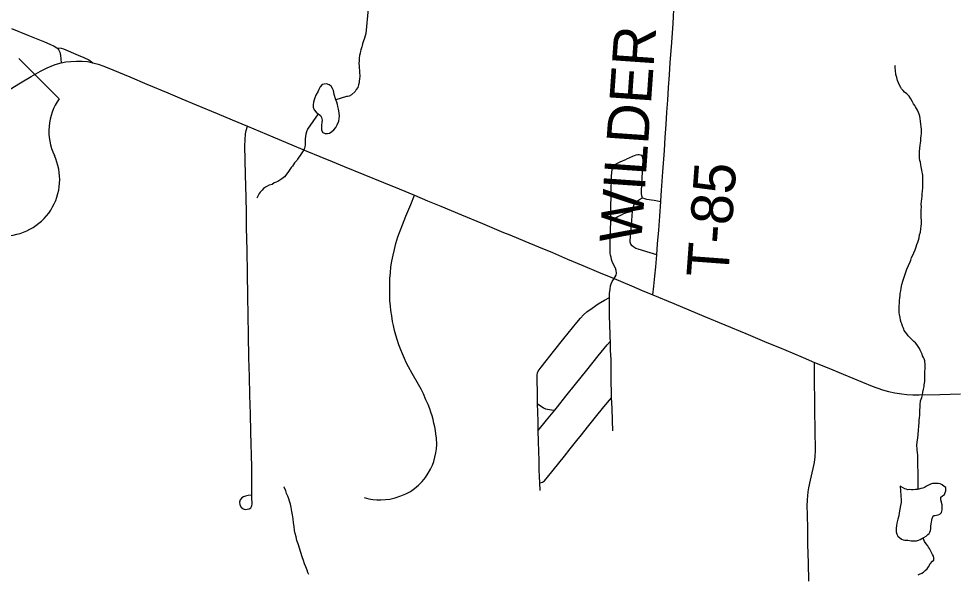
# Model space of a CAD drawing. Extents: x 103424 to 290657, y 38711 to 110967.
# Drawn here: x 127210 to 133964, y 99466 to 103483 of the extents above; entities that cross this region are included whole.
import ezdxf

# ---------------------------------------------------------------- set-up
doc = ezdxf.new("R2010")
doc.units = 0
for name, color, linetype in [('GM_X_County_Road', 7, 'Continuous'), ('GM_X_Minor_Lake', 7, 'Continuous'), ('GM_X_Minor_River', 7, 'Continuous'), ('GM_X_Township_Road', 7, 'Continuous'), ('GM_X_Township_Road_Text', 7, 'Continuous'), ('GM_X_US_Route', 7, 'Continuous'), ('GM_X_US_Shield', 7, 'Continuous')]:
    doc.layers.add(name, color=color, linetype=linetype)

msp = doc.modelspace()

# ---------------------------------------------------------------- linework, layer by layer
at = {"layer": 'GM_X_County_Road'}
for points in [[(127159.4, 103413.1), (127277.7, 103364.5), (127396.1, 103315.9), (127436.7, 103299), (127465.7, 103285.1), (127486.7, 103273.3), (127493.7, 103266.3), (127501.1, 103256), (127507.9, 103241.4), (127513.3, 103217.3), (127515.7, 103193.2), (127516.5, 103163.7)], [(127486.7, 103273.3), (127516.6, 103270), (127533.5, 103264.5), (127641.3, 103218.6), (127681, 103202.4), (127717.7, 103185.4), (127747, 103165.1)]]:
    msp.add_lwpolyline(points, dxfattribs=at)
at = {"layer": 'GM_X_Minor_Lake'}
for points in [[(129503, 102896.7), (129490.7, 102934.9), (129488.5, 102951), (129484.4, 102965.1), (129478.3, 102979.1), (129468.1, 102995.2), (129453.9, 103005.2), (129435.8, 103011.1), (129417.7, 103011), (129403.6, 103006.9), (129389.6, 102990.6), (129379.7, 102972.4), (129373.7, 102958.3), (129357.8, 102929.9), (129349.9, 102911.7), (129346, 102897.6), (129340.1, 102879.4), (129338.2, 102861.3), (129338.3, 102843.1), (129344.5, 102825), (129360.7, 102807), (129374.9, 102795), (129391.1, 102783), (129399.2, 102768.9), (129403.3, 102750.8), (129401.5, 102732.6), (129397.6, 102714.5), (129397.7, 102696.3), (129399.8, 102678.2), (129408, 102660.1)], [(129408, 102660.1), (129424.1, 102654.2), (129442.2, 102654.3), (129456.3, 102656.4), (129474.4, 102668.6), (129488.4, 102678.8), (129502.3, 102697), (129512.3, 102715.3), (129524.2, 102743.6), (129527.9, 102779.9), (129523.7, 102816.2), (129521.6, 102830.3), (129517.4, 102848.4), (129515.3, 102862.5), (129509.2, 102880.6), (129503, 102896.7)], [(133587, 100003.3), (133587.9, 99986.3), (133582.3, 99964), (133578.7, 99937.7), (133573.1, 99911.3), (133569.5, 99889), (133563.9, 99864.7), (133556.3, 99836.3), (133554.7, 99816), (133550.9, 99799.8), (133551.2, 99785.7), (133551.4, 99773.5), (133555.7, 99757.5), (133564.1, 99741.4), (133590.7, 99719.7), (133600.9, 99715.8), (133613, 99714), (133623.1, 99714.2), (133635.2, 99712.4), (133647.4, 99710.6), (133659.5, 99708.8), (133675.7, 99709.1), (133697.8, 99709.5), (133711.9, 99713.8), (133723.9, 99718.1), (133737.9, 99724.4), (133751.9, 99732.7), (133767.9, 99743.1), (133779.8, 99753.4), (133789.7, 99761.7), (133795.6, 99771.9), (133799.4, 99784.1), (133801.3, 99794.2), (133803, 99812.4), (133804.6, 99832.6), (133806.4, 99842.8), (133808.2, 99856.9), (133812, 99869.1), (133821.7, 99891.5), (133831.8, 99891.7), (133841.8, 99893.9), (133855.9, 99896.2), (133868, 99900.4), (133877.8, 99912.7), (133881.7, 99922.9), (133883.5, 99933.1), (133883.3, 99943.1), (133883.1, 99955.3), (133882.9, 99969.4), (133874.2, 100003.6), (133873.8, 100023.8), (133885.7, 100034.1), (133899.7, 100044.4), (133905.5, 100056.7), (133909.3, 100070.9), (133910.9, 100093.1), (133898.7, 100101), (133884.3, 100112.9), (133870.1, 100120.7), (133853.9, 100122.4), (133843.8, 100122.2), (133833.7, 100122), (133823.6, 100121.9), (133813.5, 100121.7), (133799.5, 100117.4), (133785.5, 100111.1), (133769.5, 100102.7), (133755.5, 100094.4), (133743.5, 100090.1), (133729.4, 100085.8), (133715.4, 100081.5), (133705.3, 100079.3), (133691.2, 100079.1), (133675.1, 100076.8), (133661, 100076.5), (133648.8, 100078.3), (133636.7, 100078.1), (133624.6, 100081.9), (133614.4, 100083.8), (133579.8, 100103.4)], [(133579.8, 100103.4), (133587, 100003.3)]]:
    msp.add_lwpolyline(points, dxfattribs=at)
at = {"layer": 'GM_X_Minor_River'}
for points in [[(129736, 103553.5), (129718.2, 103376.9), (129708.5, 103342.5), (129700.7, 103316.1), (129694.8, 103302), (129693, 103289.8), (129689, 103279.7), (129683.2, 103257.4), (129679.3, 103247.3), (129677.5, 103233.1), (129673.6, 103216.9), (129671.8, 103198.7), (129670, 103180.5), (129668.2, 103160.3), (129670.4, 103142.1), (129670.6, 103126), (129672.8, 103111.9), (129673, 103093.7), (129675.3, 103069.5), (129673.6, 103047.2), (129671.7, 103033.1), (129669.8, 103020.9), (129666, 103004.7), (129660.1, 102986.5), (129650.2, 102972.3), (129642.3, 102958), (129614.3, 102933.5), (129598.2, 102923.3), (129586.2, 102921.1), (129580.1, 102921.1), (129503, 102896.7)], [(133731.9, 101983.1), (133733.6, 102001.3), (133735.1, 102027.6), (133732.8, 102043.7), (133732.5, 102057.8), (133732.3, 102072), (133732, 102086.1), (133731.7, 102102.3), (133733.4, 102120.5), (133733, 102142.7), (133734.7, 102160.9), (133736.4, 102181.1), (133738.1, 102199.3), (133739.8, 102215.5), (133741.4, 102239.8), (133743.1, 102258), (133744.7, 102278.2), (133744.4, 102298.5), (133744, 102318.6), (133743.7, 102336.8), (133743.4, 102350.9), (133741.2, 102363), (133739, 102373.1), (133736.7, 102387.2), (133734.5, 102399.3), (133732.2, 102413.4), (133729.9, 102427.5), (133727.6, 102445.6), (133723.4, 102457.7), (133721, 102473.8), (133720.7, 102491.9), (133720.4, 102510.1), (133720.1, 102524.3), (133725.4, 102568.8), (133727.2, 102583), (133728.9, 102601.2), (133730.5, 102619.4), (133732.3, 102635.6), (133734, 102651.8), (133733.7, 102665.9), (133733.4, 102684.1), (133733.1, 102702.3), (133730.7, 102720.4), (133728.3, 102742.6), (133723.9, 102762.7), (133721.6, 102778.8), (133717.3, 102792.9), (133713.1, 102804.9), (133704.7, 102823), (133698.4, 102835), (133692.2, 102845), (133685.9, 102854.9), (133677.7, 102866.9), (133669.3, 102882.9), (133656.8, 102904.9), (133644.4, 102922.9), (133627.9, 102940.8), (133611.6, 102952.6), (133601.3, 102964.5), (133590.9, 102976.5), (133584.7, 102986.4), (133572.3, 103006.4), (133568, 103018.5), (133561.6, 103036.5), (133555.2, 103058.6), (133548.7, 103078.7), (133546.2, 103109), (133543.9, 103127.1), (133543.6, 103143.3), (133545.5, 103147.3)], [(129374.9, 102795), (129298.1, 102683.9), (129290.2, 102665.7), (129286.4, 102647.5), (129280.7, 102615.1), (129280.8, 102600.9), (129281.1, 102580.7), (129281.2, 102570.6), (129277.3, 102556.5), (129275.4, 102546.3), (129267.5, 102530.1), (129261.6, 102520), (129251.6, 102505.7), (129243.7, 102493.5), (129235.8, 102481.3), (129225.8, 102467.1), (129219.9, 102456.9), (129203.9, 102440.6), (129196, 102428.4), (129188, 102418.2), (129180.1, 102408), (129170.2, 102391.8), (129160.2, 102379.6), (129148.3, 102361.3), (129130.4, 102340.9), (129112.4, 102324.5), (129098.3, 102316.3), (129082.3, 102306.1), (129070.2, 102301.9), (129056.1, 102295.7), (129042.1, 102285.5), (129020, 102279.2), (128993.9, 102264.8), (128979.9, 102254.5), (128969.9, 102244.3), (128955.9, 102230.1), (128947.9, 102219.9), (128940, 102205.7), (128934.1, 102191.5), (128930.2, 102185.4)], [(133711.2, 100080.6), (133709.7, 100180.7), (133709.2, 100213), (133708.6, 100245.4), (133707.9, 100281.7), (133707.5, 100305.9), (133707.1, 100326.1), (133704.7, 100348.3), (133702.4, 100362.4), (133702.2, 100374.5), (133701.8, 100398.8), (133703.4, 100423), (133706.9, 100451.4), (133710.5, 100477.7), (133711.9, 100508), (133715.4, 100538.4), (133717, 100562.7), (133718.7, 100578.9), (133720.4, 100599.1), (133722.2, 100613.3), (133722, 100623.4), (133721.6, 100641.5), (133723.4, 100655.7), (133725.1, 100671.9), (133724.8, 100692.1), (133728.3, 100720.4), (133735.9, 100744.8), (133741.7, 100763.1), (133743.3, 100783.3), (133749, 100805.7), (133752.7, 100823.9), (133754.5, 100836.1), (133756.3, 100848.2), (133758.1, 100860.4), (133759.7, 100880.6), (133759.4, 100898.8), (133759.2, 100908.9), (133758.9, 100925), (133760.3, 100959.4), (133762.1, 100971.6), (133761.8, 100987.7), (133759.6, 100999.8), (133757.4, 101009.8), (133753.1, 101023.9), (133748.9, 101033.9), (133742.6, 101046), (133738.4, 101058), (133734.2, 101068), (133725.8, 101086), (133719.5, 101098.1), (133711.1, 101114.1), (133700.8, 101128), (133690.5, 101140), (133680.2, 101149.9), (133665.9, 101161.7), (133649.4, 101179.6), (133639.2, 101189.5), (133628.8, 101205.5), (133618.5, 101217.5), (133610.2, 101229.4), (133606, 101239.4), (133601.7, 101251.5), (133597.5, 101261.5), (133591.2, 101277.6), (133586.9, 101287.6), (133582.6, 101303.7), (133580.3, 101321.8), (133575.8, 101343.9), (133573.5, 101360.1), (133573.1, 101384.3), (133572.7, 101406.5), (133574.4, 101426.7), (133576, 101447), (133577.7, 101465.2), (133579.4, 101481.4), (133581.2, 101497.6), (133584.9, 101515.8), (133588.6, 101534.1), (133592.1, 101560.4), (133599.7, 101586.8), (133609.3, 101615.2), (133618.9, 101643.7), (133628.5, 101672.2), (133651.7, 101725.1), (133657.6, 101737.3), (133663.3, 101757.6), (133671, 101773.9), (133678.8, 101790.2), (133688.5, 101812.6), (133696.2, 101833), (133701.9, 101851.2), (133707.7, 101867.5), (133713.5, 101881.8), (133717.3, 101898), (133720.9, 101920.3), (133726.6, 101940.6), (133730.2, 101962.9), (133731.9, 101983.1)], [(129307.2, 99464.1), (129300.9, 99480.2), (129294.7, 99496.3), (129284.3, 99520.5), (129276, 99542.6), (129267.6, 99566.8), (129259.2, 99592.9), (129248.8, 99623.1), (129240.3, 99655.4), (129229.9, 99685.6), (129221.5, 99711.8), (129215.1, 99737.9), (129208.8, 99762.1), (129204.5, 99782.3), (129200.1, 99812.5), (129195.8, 99838.8), (129193.4, 99867), (129189, 99895.3), (129184.7, 99921.5), (129180.3, 99949.7), (129174, 99973.9), (129167.7, 99994), (129163.4, 100012.2), (129155.1, 100032.3), (129146.8, 100050.4), (129140.6, 100070.5), (129128.1, 100096.7), (129126.3, 100099.9)], [(133710.5, 99463.6), (133720.5, 99467.8), (133736.6, 99474.2), (133748.5, 99482.4), (133760.4, 99492.8), (133774.3, 99505.1), (133784.2, 99519.5), (133795.9, 99541.9), (133813.7, 99562.4), (133823.6, 99568.6), (133823.4, 99584.8), (133821.1, 99596.9), (133814.8, 99608.9), (133798.1, 99642.9), (133791.9, 99652.9), (133785.6, 99662.9), (133781.4, 99672.9), (133769.1, 99686.9)], [(133769.1, 99686.9), (133756.7, 99702.8), (133745.3, 99728.7)]]:
    msp.add_lwpolyline(points, dxfattribs=at)
at = {"layer": 'GM_X_Township_Road'}
for points in [[(131919, 103167.3), (131921, 103194.1), (131929.5, 103312.1), (131939.3, 103447.7), (131946.5, 103598.3)], [(131850.6, 102167.5), (131855.5, 102240.3), (131865.9, 102377.2), (131876.4, 102531.2), (131882.3, 102624.5), (131888.2, 102717.9), (131895.1, 102806.6), (131902, 102895.4), (131907.2, 102985.8), (131912.5, 103076.2), (131919, 103167.3)], [(128890.5, 100410.2), (128888.3, 100493.8), (128884.8, 100627.2), (128881.3, 100760.6), (128877.7, 100896.2), (128874.1, 101031.7), (128871.2, 101196.7), (128868.7, 101337.4), (128866.2, 101478), (128863.3, 101643.1), (128860.4, 101808.1), (128857.4, 101973.1), (128855.5, 102082.3), (128853.6, 102191.5), (128850.1, 102356.5), (128848, 102460.7), (128845.8, 102564.9), (128848.5, 102649.7), (128854.2, 102676.1), (128862.8, 102705.4)], [(131512.8, 101603.8), (131520.7, 101615.8), (131528, 101628.8), (131531.2, 101642.9), (131528.2, 101662.7), (131522.4, 101679.2), (131511.1, 101702), (131500.3, 101728.3), (131495.5, 101743.2), (131491.2, 101758.6), (131488, 101774), (131485.5, 101789), (131483.6, 101832.2), (131484.2, 101897), (131486.3, 101953), (131489, 102021.2), (131490.3, 102102.3), (131492.7, 102223.5), (131495, 102344.6), (131496, 102371.5), (131498, 102392.7), (131502.6, 102406.9), (131509.7, 102419.6), (131519.8, 102428.2), (131533.6, 102436.3), (131555.8, 102447.2), (131602.4, 102468.2)], [(131718.8, 102189), (131712.7, 102203.2), (131711, 102219.8), (131710.2, 102237.1), (131717, 102336.7), (131723.9, 102436.3), (131724.3, 102462.1), (131718.3, 102486.4), (131712.7, 102493), (131704.6, 102497.5), (131694.5, 102499.6), (131685.2, 102499.1), (131669.7, 102495.5), (131644.9, 102485.9), (131602.4, 102468.2)], [(129707, 100021.4), (129724.1, 100016.3), (129741.5, 100012), (129769.1, 100007.7), (129798.8, 100005.6), (129827.2, 100005.2), (129862.2, 100006.6), (129893.6, 100010.6), (129932, 100019.9), (129972.2, 100033.3), (130008.7, 100048.8), (130040.6, 100065.9), (130071.2, 100086.5), (130099, 100110.8), (130125.3, 100137.5), (130149.4, 100166.9), (130169.6, 100196.8), (130186, 100226.2), (130199.8, 100254.5), (130210.1, 100282.5), (130218.8, 100314.1), (130224.8, 100344.7), (130229.5, 100373.2), (130231.2, 100405.8), (130229.3, 100454.1), (130225.8, 100480.7), (130221.5, 100507.2), (130216.5, 100533.6), (130210.7, 100559.8), (130204.5, 100585.9), (130197.4, 100611.8), (130189.6, 100637.5), (130181.1, 100663), (130168.4, 100693.7), (130153.8, 100728.9), (130134.6, 100770.3), (130117.9, 100804.1), (130098.9, 100838.6), (130053.7, 100918.1), (130028.1, 100965.3), (130011.2, 100997.8), (129997.8, 101027.5), (129983.8, 101059.5), (129971, 101090.4), (129958.2, 101125.3), (129944.8, 101164.9), (129934.9, 101196.4), (129926.8, 101229.5), (129918.6, 101265.1), (129912.8, 101294.7), (129906.4, 101334.3), (129900.6, 101373.3), (129897.1, 101406.5), (129893.6, 101442.6), (129891.9, 101481.6), (129891.3, 101521.8), (129893, 101604.4), (129896.5, 101646.3), (129900.6, 101690), (129907.6, 101730.7), (129915.7, 101773.8), (129925, 101813.4), (129936.1, 101858.8), (129950.7, 101905.4), (129967, 101950.2), (129983.3, 101993.3), (130008.9, 102055.5), (130043.8, 102140.5), (130070.6, 102206.9)], [(131820.7, 101777.2), (131773.6, 101790.9), (131687.4, 101816.3), (131669.7, 101822.9), (131654.5, 101830.5), (131643.3, 101840.1), (131634.2, 101852.3), (131630.2, 101866.5), (131628.6, 101878.6), (131638.3, 101989.5), (131647, 102092.2), (131647.9, 102107.5), (131649.9, 102120.7), (131654.5, 102132.8), (131661.6, 102145.4), (131670.2, 102156.1), (131682.3, 102166.7), (131697.5, 102176.8), (131718.8, 102189), (131731.9, 102183.9), (131747.7, 102179.4), (131801.9, 102170.4), (131850.2, 102162.3)], [(131793.2, 101486.9), (131800.4, 101549.8), (131807.7, 101623), (131814.2, 101688.7), (131820.7, 101777.2), (131827.3, 101854.5), (131835.5, 101955.3), (131843.7, 102056.2), (131850.2, 102162.3), (131850.6, 102167.5)], [(131489, 102021.2), (131516, 102038.8), (131541, 102053.6), (131562.4, 102064)], [(131562.4, 102064), (131582.3, 102073.7), (131598.6, 102080.1), (131615.3, 102085.5), (131647, 102092.2)], [(131503.7, 100503.5), (131500.7, 100578.3), (131499, 100668.2), (131494.5, 100743), (131492.9, 100899.2), (131491.4, 101003.4), (131490.9, 101017.6), (131488.1, 101087.3), (131486.4, 101152.9), (131485.7, 101177.9), (131484.9, 101202.2), (131481, 101335), (131480, 101421.8), (131478.8, 101466.4), (131480.6, 101497.4), (131483.7, 101527.7), (131487.6, 101552.2), (131491.4, 101566.8), (131498.9, 101583.7), (131512.8, 101603.8)], [(130978.2, 100073.1), (130975.4, 100128), (130973.7, 100172.8), (130972.2, 100222.6), (130970.7, 100291.2), (130969.7, 100353.1), (130967.2, 100427.7), (130965.3, 100506.4), (130963.5, 100568.9), (130962.6, 100639.9), (130960.6, 100699.1), (130958.6, 100757.9), (130956.6, 100891.7), (130957.4, 100909.1), (130960.2, 100922.7), (130965.2, 100935.7), (130984.9, 100963.9), (131021.7, 101009), (131075.5, 101077.4), (131150.3, 101170.4), (131243.8, 101286.7), (131269.3, 101317.5), (131292.2, 101341.4), (131316.6, 101363), (131353.9, 101391.5), (131398.3, 101422.4), (131443.7, 101448.5), (131478.8, 101466.4)], [(130965.3, 100506.4), (131025.7, 100579.8), (131084.1, 100653), (131103, 100676.7), (131164.5, 100753.8), (131233.8, 100841.6), (131316.9, 100943.3), (131398.5, 101044.9), (131462.3, 101124.6), (131486.4, 101152.9)], [(132919.5, 99417.4), (132916.8, 99549.4), (132914.2, 99681.4), (132912, 99790.8), (132909.6, 99900.2), (132909, 99958.5), (132910.9, 100005.7), (132912.3, 100032.6), (132915.5, 100063.3), (132920.1, 100092.2), (132933.2, 100147.9), (132952.3, 100231.8), (132960.8, 100275.6), (132965.4, 100315.6), (132968.5, 100364.9), (132966.2, 100508.7), (132963.9, 100652.6), (132963.1, 100743.8), (132962.3, 100835), (132960.8, 100998.8)], [(130975.4, 100128), (130994.8, 100131.4), (131009.6, 100141), (131032.3, 100168.6), (131072.4, 100218.3), (131154, 100321.5), (131195.8, 100372.9), (131244.1, 100433.4), (131277.9, 100475.2), (131320.5, 100529.6), (131378.4, 100601.3), (131439.4, 100676.6), (131494.5, 100743)], [(130960.6, 100699.1), (130971.2, 100691.8), (131002.6, 100670.3), (131017.7, 100663.4), (131032.2, 100659.5), (131061, 100655.9), (131084.1, 100653)], [(128889.9, 100038.9), (128868.8, 100035.7), (128850.6, 100031.5), (128835.5, 100026.6), (128821.9, 100018.5), (128811, 100005.7), (128805.3, 99988.4), (128807.8, 99967.9), (128817.5, 99951.9), (128832.2, 99940.4), (128847.6, 99935.3), (128877, 99939.1), (128887.2, 99947.4), (128895, 99961.3), (128897.5, 99976.3), (128894.9, 100021.7), (128895.3, 100089.7), (128896, 100159), (128894.4, 100242.8), (128892.7, 100326.6), (128890.5, 100410.2)]]:
    msp.add_lwpolyline(points, dxfattribs=at)
at = {"layer": 'GM_X_US_Route'}
for points in [[(127148.4, 102974.8), (127223.9, 103020.1), (127299.5, 103065.4), (127367.8, 103102.9), (127415.6, 103127.2), (127475.1, 103151), (127516.5, 103163.7), (127550.6, 103170.2), (127586.9, 103174.3), (127628.3, 103175.8), (127670.2, 103175.3), (127708, 103172.7), (127747, 103165.1), (127784, 103154.1), (127824.9, 103139.1), (127890.7, 103113.7), (128013.5, 103062.1), (128136.3, 103010.5), (128288.5, 102946.6), (128390.2, 102903.9), (128491.9, 102861.2), (128644.1, 102797.3), (128753.4, 102751.4), (128862.8, 102705.4)], [(127148.4, 102974.8), (127223.9, 103020.1), (127299.5, 103065.4), (127367.8, 103102.9), (127415.6, 103127.2), (127475.1, 103151), (127516.5, 103163.7), (127550.6, 103170.2), (127586.9, 103174.3), (127628.3, 103175.8), (127670.2, 103175.3), (127708, 103172.7), (127747, 103165.1), (127784, 103154.1), (127824.9, 103139.1), (127890.7, 103113.7), (128013.5, 103062.1), (128136.3, 103010.5), (128288.5, 102946.6), (128390.2, 102903.9), (128491.9, 102861.2), (128644.1, 102797.3), (128753.4, 102751.4), (128862.8, 102705.4)], [(128862.8, 102705.4), (128955.1, 102666.8), (129047.5, 102628.1), (129200.1, 102565.2), (129293.8, 102526.5), (129387.4, 102487.9), (129475.4, 102451.1), (129563.3, 102414.3), (129705.5, 102356.2), (129847.7, 102298.1), (129959.1, 102252.5), (130070.6, 102206.9), (130165.4, 102167.5), (130260.2, 102128), (130411.4, 102065), (130562.5, 102002), (130714.9, 101938.5), (130759.1, 101920.1)], [(128862.8, 102705.4), (128955.1, 102666.8), (129047.5, 102628.1), (129200.1, 102565.2), (129293.8, 102526.5), (129387.4, 102487.9), (129475.4, 102451.1), (129563.3, 102414.3), (129705.5, 102356.2), (129847.7, 102298.1), (129959.1, 102252.5), (130070.6, 102206.9), (130165.4, 102167.5), (130260.2, 102128), (130411.4, 102065), (130562.5, 102002), (130714.9, 101938.5), (130759.1, 101920.1)], [(130759.1, 101920.1), (130867.2, 101875), (130967, 101833.4), (131066.8, 101791.8), (131177.4, 101745.9), (131287.9, 101699.8), (131400.4, 101651.8), (131512.8, 101603.8), (131638.7, 101551.6), (131716, 101519.3), (131793.2, 101486.9), (131945.6, 101423.4), (132053.2, 101378.6), (132160.8, 101333.8), (132313.1, 101270.2), (132465.5, 101206.6), (132617.7, 101142.9), (132708.7, 101104.9), (132799.7, 101066.9), (132880.3, 101032.8), (132960.8, 100998.8), (133064.1, 100955.7), (133167.5, 100912.5), (133307.4, 100854.7), (133378.1, 100826.6), (133452.5, 100800), (133496.1, 100788.9), (133542.7, 100778.8), (133591.3, 100771.2), (133627.7, 100767.4), (133672, 100765), (133717.4, 100764.3), (133867.1, 100767.5), (134016.8, 100770.6)], [(130759.1, 101920.1), (130867.2, 101875), (130967, 101833.4), (131066.8, 101791.8), (131177.4, 101745.9), (131287.9, 101699.8), (131400.4, 101651.8), (131512.8, 101603.8), (131638.7, 101551.6), (131716, 101519.3), (131793.2, 101486.9), (131945.6, 101423.4), (132053.2, 101378.6), (132160.8, 101333.8), (132313.1, 101270.2), (132465.5, 101206.6), (132617.7, 101142.9), (132708.7, 101104.9), (132799.7, 101066.9), (132880.3, 101032.8), (132960.8, 100998.8), (133064.1, 100955.7), (133167.5, 100912.5), (133307.4, 100854.7), (133378.1, 100826.6), (133452.5, 100800), (133496.1, 100788.9), (133542.7, 100778.8), (133591.3, 100771.2), (133627.7, 100767.4), (133672, 100765), (133717.4, 100764.3), (133867.1, 100767.5), (134016.8, 100770.6)]]:
    msp.add_lwpolyline(points, dxfattribs=at)
at = {"layer": 'GM_X_US_Shield'}
msp.add_line((127502.3, 102904.8), (127210.5, 103196.6), dxfattribs=at)
for centre, start, end in [((127837, 102670.4), 144.99907, 205.45288), ((127098.3, 102321), 269.36174, 25.16808)]:
    msp.add_arc(centre, 408.6, start, end, dxfattribs=at)

# ---------------------------------------------------------------- texts
at = {"layer": 'GM_X_Township_Road_Text'}
for s, rotation, p in [('WILDER', 85.99992, (131708.6, 101853.5)), ('T-85', 85.76545, (132336.4, 101604.5))]:
    msp.add_text(s, height=301.87, rotation=rotation, dxfattribs=at).set_placement(p)

doc.saveas('drawing.dxf')
